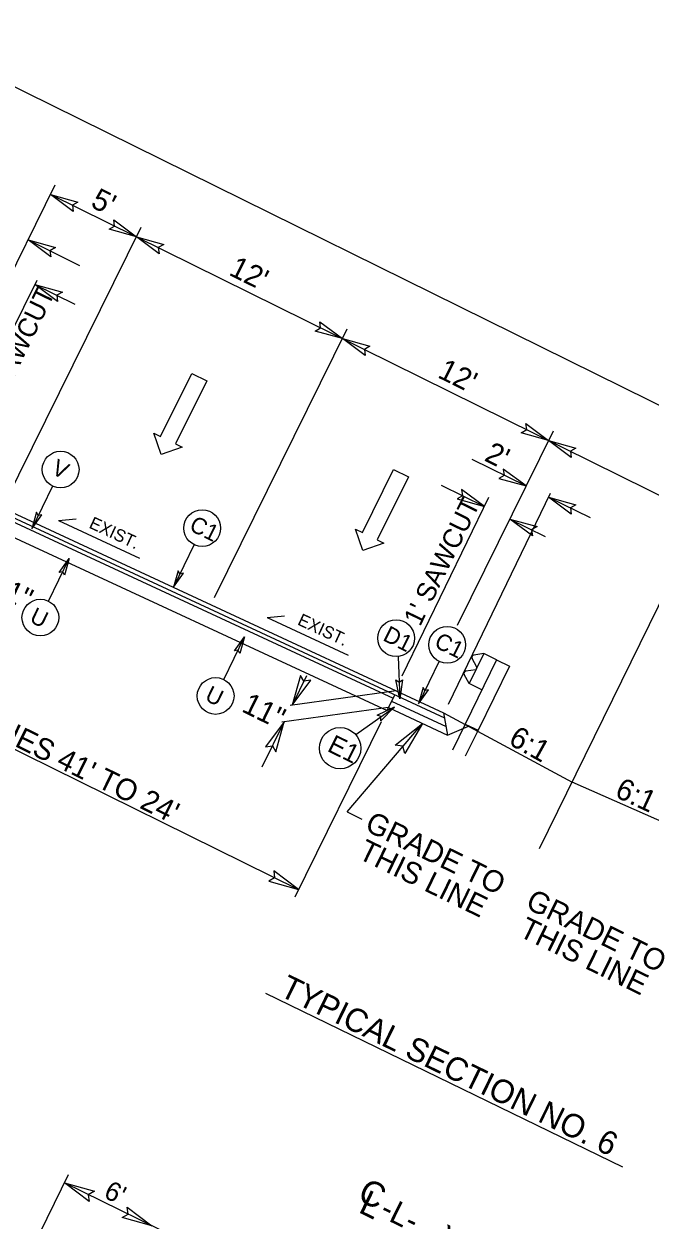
# Model space of a CAD drawing. Extents: x 1518247 to 1523638, y 635234 to 639927.
# Drawn here: x 1520253 to 1520579, y 635923 to 636547 of the extents above; entities that cross this region are included whole.
import ezdxf

# ---------------------------------------------------------------- set-up
doc = ezdxf.new("R2010")
doc.units = 0
for name, color, linetype in [('DTM TIN Hull White', 7, 'Continuous'), ('Prop Dimension', 7, 'Continuous'), ('Prop Dimension Text', 7, 'Continuous'), ('Prop Lane Arrow CELL', 7, 'Continuous'), ('Prop Shade Light', 7, 'Continuous'), ('Typical Guardrail CELL', 7, 'Continuous'), ('Typical Hinge Slope Interstate CELL', 7, 'Continuous'), ('Typical ID Circle CELL', 7, 'Continuous'), ('Typical Pavement Slope CELL', 7, 'Continuous'), ('Typical Pavement Slope Information CELL', 7, 'Continuous'), ('Typical Shoulder Slope CELL', 7, 'Continuous'), ('Typical Text Centerline CELL', 7, 'Continuous'), ('Typical Text General CELL', 7, 'Continuous'), ('Typical Text ID Circle CELL', 7, 'Continuous'), ('Typical Text Label CELL', 7, 'Continuous')]:
    doc.layers.add(name, color=color, linetype=linetype)

# ---------------------------------------------------------------- blocks, each defined once
blk = doc.blocks.new('TERMINATOR')
at = {"layer": 'Prop Shade Light'}
blk.add_lwpolyline([(-0.469, 0.081), (0, 0), (-0.471, -0.083), (-0.411, 0)], close=True, dxfattribs=at)

msp = doc.modelspace()

# ---------------------------------------------------------------- linework, layer by layer
at = {"layer": 'DTM TIN Hull White'}
for p, q in [((1520206.53, 636306.08), (1520445.19, 636195.23)), ((1520203.37, 636299.47), (1520442.09, 636188.87)), ((1520442.09, 636188.87), (1520445.19, 636195.23))]:
    msp.add_line(p, q, dxfattribs=at)
at = {"layer": 'Prop Dimension'}
for p, q in [((1520181.21, 636547.04), (1521070.13, 636107.93)), ((1520216.48, 636356.89), (1520268.98, 636463.17)), ((1520266.37, 636458.15), (1520947.73, 636121.57)), ((1520242.82, 636297.35), (1520313.8, 636441.03)), ((1520254.74, 636434.35), (1520281.6, 636421.08)), ((1520210.14, 636313.5), (1520259.46, 636413.34)), ((1520258.36, 636411.11), (1520279.15, 636400.85)), ((1520352.13, 636247.79), (1520421.34, 636387.91)), ((1520478.77, 636233.34), (1520528.88, 636334.78)), ((1520486.25, 636319.99), (1520514.64, 636305.96)), ((1520470.38, 636306.38), (1520492.87, 636295.27)), ((1520450.04, 636206.81), (1520495.21, 636300.11)), ((1520474.07, 636192.11), (1520527.38, 636302.22)), ((1520526.38, 636300.16), (1520547.99, 636289.49)), ((1520506.13, 636288.72), (1520524.64, 636279.58)), ((1520160.17, 636211.82), (1520395.92, 636095.36)), ((1520400.04, 636206.89), (1520392.58, 636191.6)), ((1520446.9, 636199.11), (1520391.53, 636191.46)), ((1520442.62, 636190.36), (1520387.25, 636182.7)), ((1520388.31, 636182.85), (1520376.74, 636159.16)), ((1520394.08, 636091.63), (1520439.24, 636183.05)), ((1520421.19, 636135.94), (1520460.61, 636182.06)), ((1520421.19, 636135.94), (1520428.88, 636132.12)), ((1520223.86, 635840.54), (1520275.91, 635946.77)), ((1520405.39, 635878), (1520273.71, 635942.29))]:
    msp.add_line(p, q, dxfattribs=at)
at = {"layer": 'Prop Lane Arrow CELL'}
for p, q in [((1520323.93, 636331.75), (1520340.21, 636364.71)), ((1520347.98, 636360.87), (1520331.7, 636327.91)), ((1520340.21, 636364.71), (1520347.98, 636360.87)), ((1520324.27, 636322.36), (1520320.4, 636333.49)), ((1520320.4, 636333.49), (1520323.93, 636331.75)), ((1520331.7, 636327.91), (1520335.23, 636326.17)), ((1520335.23, 636326.17), (1520324.27, 636322.36)), ((1520429.19, 636281.65), (1520445.48, 636314.61)), ((1520453.24, 636310.78), (1520436.96, 636277.82)), ((1520445.48, 636314.61), (1520453.24, 636310.78)), ((1520429.53, 636272.26), (1520425.66, 636283.4)), ((1520425.66, 636283.4), (1520429.19, 636281.65)), ((1520440.49, 636276.07), (1520429.53, 636272.26)), ((1520436.96, 636277.82), (1520440.49, 636276.07))]:
    msp.add_line(p, q, dxfattribs=at)
at = {"layer": 'Prop Shade Light'}
for points in [[(1520259.2, 636292.28), (1520256.68, 636283.63), (1520262.01, 636290.96), (1520260.09, 636290.63)], [(1520271.01, 636260.82), (1520276.29, 636268.12), (1520273.78, 636259.41), (1520272.86, 636261.12)], [(1520333.09, 636261.76), (1520330.57, 636253.11), (1520335.9, 636260.44), (1520333.99, 636260.12)], [(1520362.47, 636219.95), (1520367.75, 636227.25), (1520365.24, 636218.54), (1520364.32, 636220.25)], [(1520450.11, 636204.87), (1520448.76, 636194.83), (1520446.62, 636204.8), (1520448.44, 636203.59)], [(1520460.95, 636200.87), (1520458.43, 636192.22), (1520463.76, 636199.55), (1520461.85, 636199.22)], [(1520436.89, 636186.3), (1520446.03, 636190.68), (1520438.87, 636183.42), (1520438.88, 636185.6)]]:
    msp.add_lwpolyline(points, close=True, dxfattribs=at)
at = {"layer": 'Typical Guardrail CELL'}
for p, q in [((1520492.52, 636218.53), (1520484.88, 636202.91)), ((1520489.01, 636211.35), (1520486.45, 636215.99)), ((1520492.52, 636218.53), (1520487.29, 636217.71)), ((1520499.22, 636215.26), (1520492.52, 636218.53)), ((1520499.22, 636215.26), (1520482.84, 636181.76)), ((1520488.39, 636210.09), (1520483.16, 636209.26)), ((1520488.7, 636210.72), (1520488.39, 636210.09)), ((1520488.7, 636210.72), (1520489.01, 636211.35)), ((1520505.93, 636211.98), (1520489.55, 636178.49)), ((1520499.22, 636215.26), (1520505.93, 636211.98)), ((1520484.88, 636202.91), (1520482.32, 636207.55)), ((1520491.58, 636199.63), (1520484.88, 636202.91)), ((1520482.84, 636181.76), (1520476.2, 636168.18)), ((1520482.84, 636181.76), (1520489.55, 636178.49)), ((1520489.55, 636178.49), (1520482.9, 636164.9))]:
    msp.add_line(p, q, dxfattribs=at)
for centre, start, end in [((1520487.46, 636216.56), 98.9407, 208.94893), ((1520483.33, 636208.11), 98.94362, 208.97432)]:
    msp.add_arc(centre, 1.16, start, end, dxfattribs=at)
at = {"layer": 'Typical Hinge Slope Interstate CELL'}
for p, q in [((1520471.58, 636187.61), (1520473.67, 636175.99)), ((1520473.67, 636175.99), (1520484.57, 636180.59))]:
    msp.add_line(p, q, dxfattribs=at)
for points in [[(1520446.06, 636197.04), (1520443.43, 636191.62), (1520442.8, 636190.34)], [(1520471.58, 636187.61), (1520538.68, 636151.37)], [(1520609.23, 636120.29), (1520538.68, 636151.37)]]:
    msp.add_lwpolyline(points, dxfattribs=at)
at = {"layer": 'Typical ID Circle CELL'}
for p, q in [((1520267.54, 636305.9), (1520256.68, 636283.63)), ((1520341.44, 636275.38), (1520330.57, 636253.11)), ((1520265.39, 636245.87), (1520276.29, 636268.12)), ((1520356.85, 636205), (1520367.75, 636227.25)), ((1520447.83, 636216.87), (1520448.76, 636194.83)), ((1520469.3, 636214.48), (1520458.43, 636192.22)), ((1520425.75, 636176.28), (1520445.95, 636190.6))]:
    msp.add_line(p, q, dxfattribs=at)
for centre, radius in [((1520271.75, 636314.51), 9.59), ((1520345.64, 636283.99), 9.59), ((1520261.17, 636237.27), 9.59), ((1520446.8, 636226.54), 9.59), ((1520473.5, 636223.1), 9.59), ((1520352.63, 636196.39), 9.59), ((1520417.59, 636169.15), 10.78)]:
    msp.add_circle(centre, radius, dxfattribs=at)
at = {"layer": 'Typical Pavement Slope CELL'}
for p, q in [((1520207.3, 636307.94), (1520472.05, 636184.96)), ((1520241.43, 636294.52), (1520350.24, 636243.97)), ((1520350.24, 636243.97), (1520471.58, 636187.61))]:
    msp.add_line(p, q, dxfattribs=at)
at = {"layer": 'Typical Pavement Slope Information CELL'}
for p, q in [((1520270.69, 636287.94), (1520279.8, 636288.75)), ((1520270.69, 636287.94), (1520312.96, 636268.3)), ((1520379.5, 636237.39), (1520388.61, 636238.2)), ((1520379.5, 636237.39), (1520421.78, 636217.75))]:
    msp.add_line(p, q, dxfattribs=at)
at = {"layer": 'Typical Shoulder Slope CELL'}
for p, q in [((1520444.45, 636193.72), (1520472.86, 636180.52)), ((1520442.8, 636190.34), (1520473.67, 636175.99))]:
    msp.add_line(p, q, dxfattribs=at)
at = {"layer": 'Typical Text Centerline CELL'}
msp.add_line((1520521.7, 636116.72), (1520603.88, 636284.44), dxfattribs=at)
at = {"layer": 'Typical Text Label CELL'}
msp.add_line((1520378.71, 636041.28), (1520564.92, 635950.66), dxfattribs=at)

# ---------------------------------------------------------------- block references
at = {"layer": 'Prop Dimension'}
for p, xscale, yscale, rotation in [((1520266.48, 636458.1), 30.9388560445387, 33.305184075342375, 153.71146049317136), ((1520311.3, 636435.96), 30.9388560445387, 33.305184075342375, -26.28853950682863), ((1520254.74, 636434.35), 30.9388560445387, 33.305184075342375, 153.71146049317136), ((1520311.3, 636435.96), 30.9388560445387, 33.305184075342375, 153.71146049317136), ((1520258.36, 636411.11), 30.9388560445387, 33.305184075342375, 153.71146049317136), ((1520418.84, 636382.84), 30.9388560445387, 33.305184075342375, -26.28853950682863), ((1520418.84, 636382.84), 30.9388560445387, 33.305184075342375, 153.71146049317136), ((1520526.38, 636329.72), 30.9388560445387, 33.305184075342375, -26.28853950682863), ((1520526.38, 636329.72), 30.9388560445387, 33.305184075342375, 153.71146049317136), ((1520514.64, 636305.96), 30.938856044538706, -33.30518407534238, -25.836011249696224), ((1520492.87, 636295.27), 30.938856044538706, -33.30518407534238, -25.836011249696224), ((1520526.38, 636300.16), 30.9388560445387, 33.305184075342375, 153.71146049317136), ((1520506.13, 636288.72), 30.9388560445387, 33.305184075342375, 153.71146049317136), ((1520392.58, 636191.6), 33.82820784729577, -36.415525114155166, -115.99597801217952), ((1520388.31, 636182.85), 33.82820784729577, -36.41552511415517, 64.0796934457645), ((1520460.62, 636182.06), 38.042534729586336, 40.952180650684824, 48.91771213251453), ((1520395.92, 636095.36), 33.82820784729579, -36.41552511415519, -26.020730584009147), ((1520273.71, 635942.29), 33.82820784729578, 36.41552511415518, 153.89617982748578), ((1520319.43, 635919.97), 33.82820784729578, 36.41552511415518, -26.103820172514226)]:
    msp.add_blockref('TERMINATOR', p, dxfattribs=dict(at, xscale=xscale, yscale=yscale, rotation=rotation))

# ---------------------------------------------------------------- texts
for s, height, rotation, p in [("5'", 11.189, 333.71146, (1520286.86, 636451.82)), ("12'", 11.189, 333.71146, (1520358.99, 636416.32)), ("1' SAWCUT", 10, 63.93772, (1520237.54, 636342.3)), ("12'", 11.189, 333.71146, (1520467.92, 636362.87)), ("2'", 11.189, 333.71146, (1520492.29, 636319.44)), ("1' SAWCUT", 10, 63.93772, (1520459.3, 636232.26)), ('11"', 11.189, 333.71146, (1520233.92, 636250.84)), ('11"', 11.189, 333.71146, (1520365.64, 636188.55)), ("VARIES 41' TO 24'", 11.1894, 333.71146, (1520215.97, 636185.86)), ('6:1', 11.189, 330.90495, (1520504.85, 636171.53)), ('6:1', 11.189, 335.19229, (1520560.34, 636144.05)), ("6'", 9.969, 333.89618, (1520293.68, 635934.96))]:
    msp.add_text(s, height=height, rotation=rotation, dxfattribs=at).set_placement(p)
at = {"layer": 'Prop Dimension Text'}
for s, height, rotation, p in [('TYPICAL SECTION NO. 6', 12.2298, 334.0511, (1520385.3, 636040.28)), ('-L-, -Y2-, -LPC-', 11.9625, 333.89618, (1520437.65, 635925.05))]:
    msp.add_text(s, height=height, rotation=rotation, dxfattribs=at).set_placement(p)
at = {"layer": 'Typical Pavement Slope Information CELL'}
for p in [(1520286.09, 636284.33), (1520394.9, 636233.79)]:
    msp.add_text('EXIST.', height=6.476, rotation=335.08347, dxfattribs=at).set_placement(p)
at = {"layer": 'Typical Text Centerline CELL'}
for s, height, rotation, p in [('C', 13.08, 333.97927, (1520426.01, 635933.56)), ('L', 13.09, 334.03237, (1520426.59, 635927.24))]:
    msp.add_text(s, height=height, rotation=rotation, dxfattribs=at).set_placement(p)
at = {"layer": 'Typical Text General CELL'}
for s, p in [('GRADE TO', (1520429.85, 636126.56)), ('THIS LINE', (1520426.35, 636111.91)), ('GRADE TO', (1520513.78, 636086)), ('THIS LINE', (1520510.29, 636071.36))]:
    msp.add_text(s, height=11.211, rotation=334.0511, dxfattribs=at).set_placement(p)
at = {"layer": 'Typical Text ID Circle CELL'}
for s, height, rotation, p in [('V', 8.58, 333.97927, (1520266.45, 636312.59)), ('C1', 8.581, 333.97927, (1520338.32, 636283.06)), ('U', 8.58, 333.89618, (1520255.02, 636235.24)), ('D1', 8.581, 333.25136, (1520439.38, 636225.65)), ('C1', 8.581, 333.97927, (1520466.17, 636222.17)), ('U', 8.58, 333.89618, (1520346.48, 636194.36)), ('E1', 9.65, 333.61889, (1520410.37, 636167.88))]:
    msp.add_text(s, height=height, rotation=rotation, dxfattribs=at).set_placement(p)

doc.saveas('drawing.dxf')
